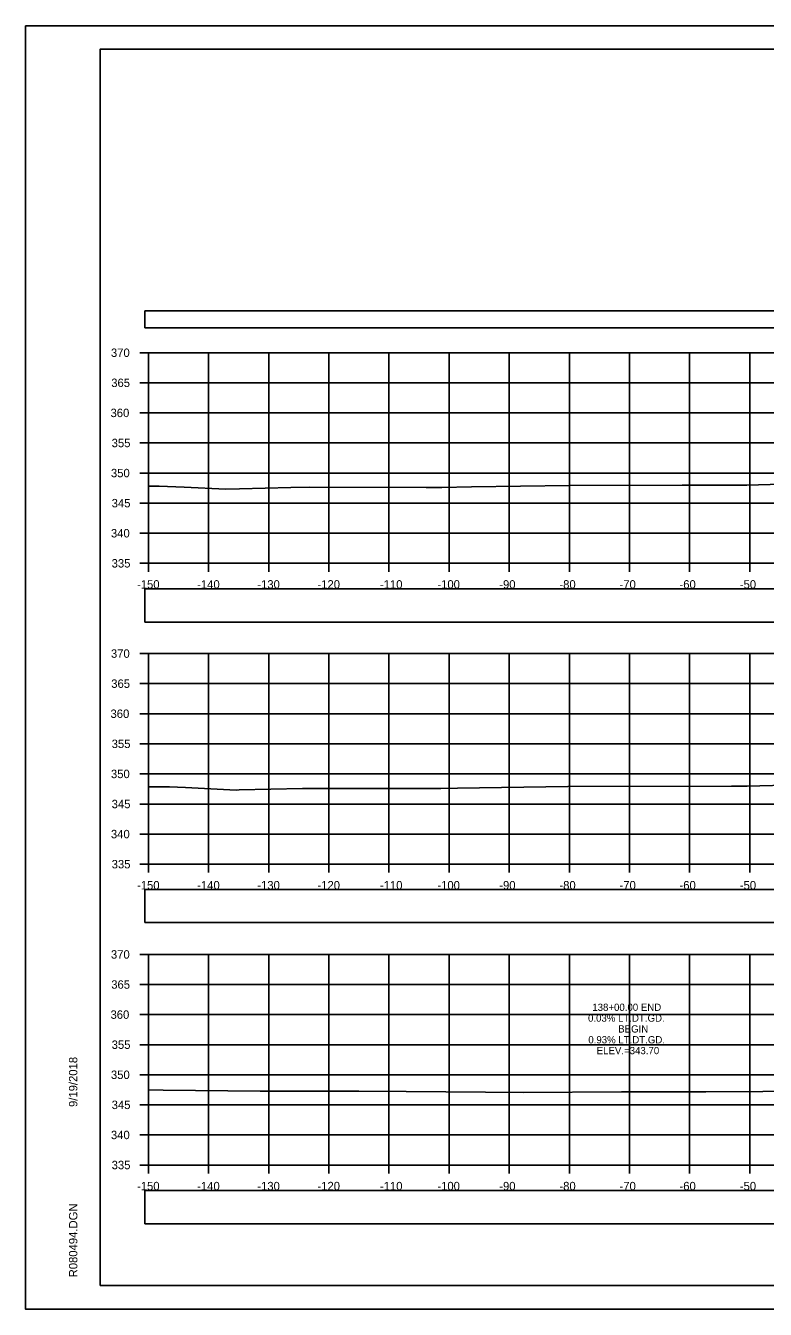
# Model space of a CAD drawing. Extents: x 1376273 to 1384221, y 378927 to 384592.
# Drawn here: x 1376887.4 to 1377010.4, y 382031.9 to 382245.2 of the extents above; entities that cross this region are included whole.
import ezdxf

# ---------------------------------------------------------------- set-up
doc = ezdxf.new("R2010")
doc.units = 0
for name, color, linetype in [('R_Axis', 7, 'Continuous'), ('R_Axis Annot', 7, 'Continuous'), ('R_Border', 7, 'Continuous'), ('R_Exist Surface', 7, 'Continuous'), ('R_Grid', 7, 'Continuous'), ('R_No Plot', 7, 'Continuous'), ('R_Xsect Elev', 7, 'Continuous')]:
    doc.layers.add(name, color=color, linetype=linetype)

msp = doc.modelspace()

# ---------------------------------------------------------------- linework, layer by layer
at = {"layer": 'R_Axis'}
for p, q in [((1376906.37, 382190.86), (1376907.77, 382190.86)), ((1376907.77, 382155.86), (1376907.77, 382190.86)), ((1376906.37, 382185.86), (1376907.77, 382185.86)), ((1376906.37, 382180.86), (1376907.77, 382180.86)), ((1376906.37, 382175.86), (1376907.77, 382175.86)), ((1376906.37, 382170.86), (1376907.77, 382170.86)), ((1376906.37, 382165.86), (1376907.77, 382165.86)), ((1376906.37, 382160.86), (1376907.77, 382160.86)), ((1376906.37, 382155.86), (1376907.77, 382155.86)), ((1376907.77, 382155.86), (1377207.77, 382155.86)), ((1376907.77, 382154.46), (1376907.77, 382155.86)), ((1376917.77, 382154.46), (1376917.77, 382155.86)), ((1376927.77, 382154.46), (1376927.77, 382155.86)), ((1376937.77, 382154.46), (1376937.77, 382155.86)), ((1376947.77, 382154.46), (1376947.77, 382155.86)), ((1376957.77, 382154.46), (1376957.77, 382155.86)), ((1376967.77, 382154.46), (1376967.77, 382155.86)), ((1376977.77, 382154.46), (1376977.77, 382155.86)), ((1376987.77, 382154.46), (1376987.77, 382155.86)), ((1376997.77, 382154.46), (1376997.77, 382155.86)), ((1377007.77, 382154.46), (1377007.77, 382155.86)), ((1376906.37, 382140.86), (1376907.77, 382140.86)), ((1376907.77, 382105.86), (1376907.77, 382140.86)), ((1376906.37, 382135.86), (1376907.77, 382135.86)), ((1376906.37, 382130.86), (1376907.77, 382130.86)), ((1376906.37, 382125.86), (1376907.77, 382125.86)), ((1376906.37, 382120.86), (1376907.77, 382120.86)), ((1376906.37, 382115.86), (1376907.77, 382115.86)), ((1376906.37, 382110.86), (1376907.77, 382110.86)), ((1376906.37, 382105.86), (1376907.77, 382105.86)), ((1376907.77, 382105.86), (1377207.77, 382105.86)), ((1376907.77, 382104.46), (1376907.77, 382105.86)), ((1376917.77, 382104.46), (1376917.77, 382105.86)), ((1376927.77, 382104.46), (1376927.77, 382105.86)), ((1376937.77, 382104.46), (1376937.77, 382105.86)), ((1376947.77, 382104.46), (1376947.77, 382105.86)), ((1376957.77, 382104.46), (1376957.77, 382105.86)), ((1376967.77, 382104.46), (1376967.77, 382105.86)), ((1376977.77, 382104.46), (1376977.77, 382105.86)), ((1376987.77, 382104.46), (1376987.77, 382105.86)), ((1376997.77, 382104.46), (1376997.77, 382105.86)), ((1377007.77, 382104.46), (1377007.77, 382105.86)), ((1376906.37, 382090.86), (1376907.77, 382090.86)), ((1376907.77, 382055.86), (1376907.77, 382090.86)), ((1376906.37, 382085.86), (1376907.77, 382085.86)), ((1376906.37, 382080.86), (1376907.77, 382080.86)), ((1376906.37, 382075.86), (1376907.77, 382075.86)), ((1376906.37, 382070.86), (1376907.77, 382070.86)), ((1376906.37, 382065.86), (1376907.77, 382065.86)), ((1376906.37, 382060.86), (1376907.77, 382060.86)), ((1376906.37, 382055.86), (1376907.77, 382055.86)), ((1376907.77, 382055.86), (1377207.77, 382055.86)), ((1376907.77, 382054.46), (1376907.77, 382055.86)), ((1376917.77, 382054.46), (1376917.77, 382055.86)), ((1376927.77, 382054.46), (1376927.77, 382055.86)), ((1376937.77, 382054.46), (1376937.77, 382055.86)), ((1376947.77, 382054.46), (1376947.77, 382055.86)), ((1376957.77, 382054.46), (1376957.77, 382055.86)), ((1376967.77, 382054.46), (1376967.77, 382055.86)), ((1376977.77, 382054.46), (1376977.77, 382055.86)), ((1376987.77, 382054.46), (1376987.77, 382055.86)), ((1376997.77, 382054.46), (1376997.77, 382055.86)), ((1377007.77, 382054.46), (1377007.77, 382055.86))]:
    msp.add_line(p, q, dxfattribs=at)
at = {"layer": 'R_Axis Annot'}
for points in [[(1376907.2, 382195.01), (1377209.01, 382195.01), (1377209.01, 382197.82), (1376907.2, 382197.82)], [(1376907.2, 382146.1), (1377209.01, 382146.1), (1377209.01, 382151.62), (1376907.2, 382151.62)], [(1376907.2, 382096.14), (1377209.01, 382096.14), (1377209.01, 382101.66), (1376907.2, 382101.66)], [(1376907.2, 382046.08), (1377209.01, 382046.08), (1377209.01, 382051.6), (1376907.2, 382051.6)]]:
    msp.add_lwpolyline(points, close=True, dxfattribs=at)
at = {"layer": 'R_Border'}
for p, q in [((1376899.77, 382241.32), (1377215.95, 382241.32)), ((1376899.77, 382035.86), (1376899.77, 382241.32)), ((1376899.77, 382035.86), (1376899.77, 382035.86)), ((1377215.95, 382035.86), (1376899.77, 382035.86))]:
    msp.add_line(p, q, dxfattribs=at)
at = {"layer": 'R_Exist Surface'}
for points in [[(1376907.77, 382168.71), (1376909.57, 382168.71), (1376913.72, 382168.54), (1376920.63, 382168.21), (1376922.89, 382168.26), (1376931.45, 382168.47), (1376934.58, 382168.49), (1376953.93, 382168.48), (1376956.56, 382168.47), (1376961.48, 382168.55), (1376977.78, 382168.81), (1376996.51, 382168.84), (1377007.26, 382168.87), (1377028.57, 382169.45)], [(1376907.77, 382118.69), (1376911.3, 382118.7), (1376913.95, 382118.59), (1376922.36, 382118.18), (1376922.86, 382118.2), (1376933.42, 382118.45), (1376934.16, 382118.46), (1376945.18, 382118.45), (1376955.89, 382118.45), (1376956.42, 382118.46), (1376959.14, 382118.5), (1376977.53, 382118.78), (1377004.74, 382118.82), (1377007.33, 382118.83), (1377015.79, 382119.06)], [(1376907.77, 382068.33), (1376910.2, 382068.29), (1376926.38, 382068.11), (1376928.78, 382068.11), (1376930.47, 382068.11), (1376942.74, 382068.11), (1376950.62, 382068.06), (1376963.8, 382067.97), (1376970.07, 382067.92), (1376986.44, 382068), (1376989.39, 382068.02), (1377000.45, 382068.04), (1377009.96, 382068.1), (1377020.99, 382068.11)]]:
    msp.add_lwpolyline(points, dxfattribs=at)
at = {"layer": 'R_Grid'}
for p, q in [((1376907.77, 382190.86), (1377207.77, 382190.86)), ((1376907.77, 382155.86), (1376907.77, 382190.86)), ((1376907.77, 382190.86), (1377207.77, 382190.86)), ((1376907.77, 382155.86), (1376907.77, 382190.86)), ((1376917.77, 382155.86), (1376917.77, 382190.86)), ((1376917.77, 382155.86), (1376917.77, 382190.86)), ((1376927.77, 382155.86), (1376927.77, 382190.86)), ((1376927.77, 382155.86), (1376927.77, 382190.86)), ((1376937.77, 382155.86), (1376937.77, 382190.86)), ((1376937.77, 382155.86), (1376937.77, 382190.86)), ((1376947.77, 382155.86), (1376947.77, 382190.86)), ((1376947.77, 382155.86), (1376947.77, 382190.86)), ((1376957.77, 382155.86), (1376957.77, 382190.86)), ((1376957.77, 382155.86), (1376957.77, 382190.86)), ((1376967.77, 382155.86), (1376967.77, 382190.86)), ((1376967.77, 382155.86), (1376967.77, 382190.86)), ((1376977.77, 382155.86), (1376977.77, 382190.86)), ((1376977.77, 382155.86), (1376977.77, 382190.86)), ((1376987.77, 382155.86), (1376987.77, 382190.86)), ((1376987.77, 382155.86), (1376987.77, 382190.86)), ((1376997.77, 382155.86), (1376997.77, 382190.86)), ((1376997.77, 382155.86), (1376997.77, 382190.86)), ((1377007.77, 382155.86), (1377007.77, 382190.86)), ((1377007.77, 382155.86), (1377007.77, 382190.86)), ((1376907.77, 382185.86), (1377207.77, 382185.86)), ((1376907.77, 382185.86), (1377207.77, 382185.86)), ((1376907.77, 382180.86), (1377207.77, 382180.86)), ((1376907.77, 382180.86), (1377207.77, 382180.86)), ((1376907.77, 382175.86), (1377207.77, 382175.86)), ((1376907.77, 382175.86), (1377207.77, 382175.86)), ((1376907.77, 382170.86), (1377207.77, 382170.86)), ((1376907.77, 382170.86), (1377207.77, 382170.86)), ((1376907.77, 382165.86), (1377207.77, 382165.86)), ((1376907.77, 382165.86), (1377207.77, 382165.86)), ((1376907.77, 382160.86), (1377207.77, 382160.86)), ((1376907.77, 382160.86), (1377207.77, 382160.86)), ((1376907.77, 382155.86), (1377207.77, 382155.86)), ((1376907.77, 382155.86), (1377207.77, 382155.86)), ((1376907.77, 382140.86), (1377207.77, 382140.86)), ((1376907.77, 382105.86), (1376907.77, 382140.86)), ((1376907.77, 382140.86), (1377207.77, 382140.86)), ((1376907.77, 382105.86), (1376907.77, 382140.86)), ((1376917.77, 382105.86), (1376917.77, 382140.86)), ((1376917.77, 382105.86), (1376917.77, 382140.86)), ((1376927.77, 382105.86), (1376927.77, 382140.86)), ((1376927.77, 382105.86), (1376927.77, 382140.86)), ((1376937.77, 382105.86), (1376937.77, 382140.86)), ((1376937.77, 382105.86), (1376937.77, 382140.86)), ((1376947.77, 382105.86), (1376947.77, 382140.86)), ((1376947.77, 382105.86), (1376947.77, 382140.86)), ((1376957.77, 382105.86), (1376957.77, 382140.86)), ((1376957.77, 382105.86), (1376957.77, 382140.86)), ((1376967.77, 382105.86), (1376967.77, 382140.86)), ((1376967.77, 382105.86), (1376967.77, 382140.86)), ((1376977.77, 382105.86), (1376977.77, 382140.86)), ((1376977.77, 382105.86), (1376977.77, 382140.86)), ((1376987.77, 382105.86), (1376987.77, 382140.86)), ((1376987.77, 382105.86), (1376987.77, 382140.86)), ((1376997.77, 382105.86), (1376997.77, 382140.86)), ((1376997.77, 382105.86), (1376997.77, 382140.86)), ((1377007.77, 382105.86), (1377007.77, 382140.86)), ((1377007.77, 382105.86), (1377007.77, 382140.86)), ((1376907.77, 382135.86), (1377207.77, 382135.86)), ((1376907.77, 382135.86), (1377207.77, 382135.86)), ((1376907.77, 382130.86), (1377207.77, 382130.86)), ((1376907.77, 382130.86), (1377207.77, 382130.86)), ((1376907.77, 382125.86), (1377207.77, 382125.86)), ((1376907.77, 382125.86), (1377207.77, 382125.86)), ((1376907.77, 382120.86), (1377207.77, 382120.86)), ((1376907.77, 382120.86), (1377207.77, 382120.86)), ((1376907.77, 382115.86), (1377207.77, 382115.86)), ((1376907.77, 382115.86), (1377207.77, 382115.86)), ((1376907.77, 382110.86), (1377207.77, 382110.86)), ((1376907.77, 382110.86), (1377207.77, 382110.86)), ((1376907.77, 382105.86), (1377207.77, 382105.86)), ((1376907.77, 382105.86), (1377207.77, 382105.86)), ((1376907.77, 382090.86), (1377207.77, 382090.86)), ((1376907.77, 382055.86), (1376907.77, 382090.86)), ((1376907.77, 382090.86), (1377207.77, 382090.86)), ((1376907.77, 382055.86), (1376907.77, 382090.86)), ((1376917.77, 382055.86), (1376917.77, 382090.86)), ((1376917.77, 382055.86), (1376917.77, 382090.86)), ((1376927.77, 382055.86), (1376927.77, 382090.86)), ((1376927.77, 382055.86), (1376927.77, 382090.86)), ((1376937.77, 382055.86), (1376937.77, 382090.86)), ((1376937.77, 382055.86), (1376937.77, 382090.86)), ((1376947.77, 382055.86), (1376947.77, 382090.86)), ((1376947.77, 382055.86), (1376947.77, 382090.86)), ((1376957.77, 382055.86), (1376957.77, 382090.86)), ((1376957.77, 382055.86), (1376957.77, 382090.86)), ((1376967.77, 382055.86), (1376967.77, 382090.86)), ((1376967.77, 382055.86), (1376967.77, 382090.86)), ((1376977.77, 382055.86), (1376977.77, 382090.86)), ((1376977.77, 382055.86), (1376977.77, 382090.86)), ((1376987.77, 382055.86), (1376987.77, 382090.86)), ((1376987.77, 382055.86), (1376987.77, 382090.86)), ((1376997.77, 382055.86), (1376997.77, 382090.86)), ((1376997.77, 382055.86), (1376997.77, 382090.86)), ((1377007.77, 382055.86), (1377007.77, 382090.86)), ((1377007.77, 382055.86), (1377007.77, 382090.86)), ((1376907.77, 382085.86), (1377207.77, 382085.86)), ((1376907.77, 382085.86), (1377207.77, 382085.86)), ((1376907.77, 382080.86), (1377207.77, 382080.86)), ((1376907.77, 382080.86), (1377207.77, 382080.86)), ((1376907.77, 382075.86), (1377207.77, 382075.86)), ((1376907.77, 382075.86), (1377207.77, 382075.86)), ((1376907.77, 382070.86), (1377207.77, 382070.86)), ((1376907.77, 382070.86), (1377207.77, 382070.86)), ((1376907.77, 382065.86), (1377207.77, 382065.86)), ((1376907.77, 382065.86), (1377207.77, 382065.86)), ((1376907.77, 382060.86), (1377207.77, 382060.86)), ((1376907.77, 382060.86), (1377207.77, 382060.86)), ((1376907.77, 382055.86), (1377207.77, 382055.86)), ((1376907.77, 382055.86), (1377207.77, 382055.86))]:
    msp.add_line(p, q, dxfattribs=at)
at = {"layer": 'R_No Plot'}
for p, q in [((1376887.37, 382245.21), (1377220.7, 382245.21)), ((1376887.37, 382031.88), (1377220.7, 382031.88))]:
    msp.add_line(p, q, dxfattribs=at)
for points in [[(1376887.36, 382245.21), (1377220.7, 382245.21), (1377220.7, 382031.88), (1376887.36, 382031.88)], [(1377133.69, 382241.32), (1377133.69, 382231.44), (1377169.42, 382231.44), (1377169.42, 382228.52), (1377192.62, 382228.52), (1377192.62, 382204.19), (1377215.95, 382204.19), (1377215.95, 382035.86), (1376899.77, 382035.86), (1376899.77, 382241.32)]]:
    msp.add_lwpolyline(points, close=True, dxfattribs=at)

# ---------------------------------------------------------------- texts
at = {"layer": 'R_Axis Annot'}
for s, p in [('370', (1376901.54, 382190.16)), ('365', (1376901.59, 382185.16)), ('360', (1376901.47, 382180.16)), ('355', (1376901.66, 382175.16)), ('350', (1376901.54, 382170.16)), ('345', (1376901.66, 382165.16)), ('340', (1376901.54, 382160.16)), ('335', (1376901.66, 382155.16)), ('-150', (1376905.88, 382151.66)), ('-140', (1376915.88, 382151.66)), ('-130', (1376925.88, 382151.66)), ('-120', (1376935.88, 382151.66)), ('-110', (1376946.27, 382151.66)), ('-100', (1376955.82, 382151.66)), ('-90', (1376966.11, 382151.66)), ('-80', (1376976.11, 382151.66)), ('-70', (1376986.11, 382151.66)), ('-60', (1376996.08, 382151.66)), ('-50', (1377006.11, 382151.66)), ('370', (1376901.54, 382140.16)), ('365', (1376901.59, 382135.16)), ('360', (1376901.47, 382130.16)), ('355', (1376901.66, 382125.16)), ('350', (1376901.54, 382120.16)), ('345', (1376901.66, 382115.16)), ('340', (1376901.54, 382110.16)), ('335', (1376901.66, 382105.16)), ('-150', (1376905.88, 382101.66)), ('-140', (1376915.88, 382101.66)), ('-130', (1376925.88, 382101.66)), ('-120', (1376935.88, 382101.66)), ('-110', (1376946.27, 382101.66)), ('-100', (1376955.82, 382101.66)), ('-90', (1376966.11, 382101.66)), ('-80', (1376976.11, 382101.66)), ('-70', (1376986.11, 382101.66)), ('-60', (1376996.08, 382101.66)), ('-50', (1377006.11, 382101.66)), ('370', (1376901.54, 382090.16)), ('365', (1376901.59, 382085.16)), ('360', (1376901.47, 382080.16)), ('355', (1376901.66, 382075.16)), ('350', (1376901.54, 382070.16)), ('345', (1376901.66, 382065.16)), ('340', (1376901.54, 382060.16)), ('335', (1376901.66, 382055.16)), ('-150', (1376905.88, 382051.66)), ('-140', (1376915.88, 382051.66)), ('-130', (1376925.88, 382051.66)), ('-120', (1376935.88, 382051.66)), ('-110', (1376946.27, 382051.66)), ('-100', (1376955.82, 382051.66)), ('-90', (1376966.11, 382051.66)), ('-80', (1376976.11, 382051.66)), ('-70', (1376986.11, 382051.66)), ('-60', (1376996.08, 382051.66)), ('-50', (1377006.11, 382051.66))]:
    msp.add_text(s, height=1.4, dxfattribs=at).set_placement(p)
at = {"layer": 'R_Border'}
for s, p in [('9/19/2018', (1376895.96, 382065.5)), ('R080494.DGN', (1376895.96, 382037.19))]:
    msp.add_text(s, height=1.4, rotation=90, dxfattribs=at).set_placement(p)
at = {"layer": 'R_Xsect Elev'}
for s, p in [('138+00.00 END', (1376981.58, 382081.48)), ('0.03% LT.DT.GD.', (1376980.87, 382079.68)), ('0.93% LT.DT.GD.', (1376980.92, 382076.08)), ('BEGIN', (1376985.89, 382077.88)), ('ELEV.=343.70', (1376982.31, 382074.28))]:
    msp.add_text(s, height=1.2, rotation=360, dxfattribs=at).set_placement(p)

doc.saveas('drawing.dxf')
